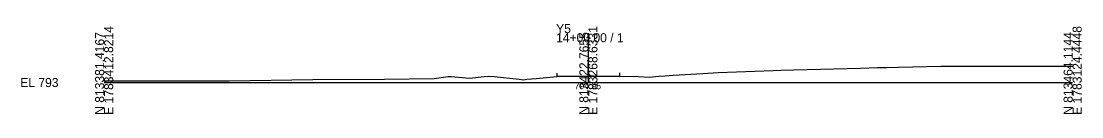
# Model space of a CAD drawing. Extents: x -26 to 1603, y -10 to 6526.
# Drawn here: x 1274.3 to 1602.8, y 990.3 to 1018.1 of the extents above; entities that cross this region are included whole.
import ezdxf

# ---------------------------------------------------------------- set-up
doc = ezdxf.new("R2010")
doc.units = 0
for name, color, linetype in [('Exist Cross Section Cell', 7, 'Continuous'), ('Exist XS Center Line Elevation Label', 7, 'Continuous'), ('Exist XS Ground Line', 7, 'Continuous'), ('Prop XS EOT Tick Mark', 7, 'Continuous'), ('Prop XS Finish Grade Pavement', 7, 'Continuous')]:
    doc.layers.add(name, color=color, linetype=linetype)

msp = doc.modelspace()

# ---------------------------------------------------------------- linework, layer by layer
at = {"layer": 'Exist Cross Section Cell'}
for p, q in [((1450, 1000), (1450, 1015.28)), ((1300, 1000), (1450, 1000)), ((1450, 1000), (1600, 1000))]:
    msp.add_line(p, q, dxfattribs=at)
at = {"layer": 'Exist XS Ground Line'}
for p, q in [((1471.79, 1001.96), (1473.77, 1002.12)), ((1473.77, 1002.12), (1476.26, 1002.26)), ((1476.26, 1002.26), (1485.48, 1002.82)), ((1485.48, 1002.82), (1490.18, 1003.07)), ((1490.18, 1003.07), (1507.29, 1003.73)), ((1507.29, 1003.73), (1509.58, 1003.8)), ((1509.58, 1003.8), (1513.66, 1003.91)), ((1513.66, 1003.91), (1534.25, 1004.49)), ((1534.25, 1004.49), (1539.57, 1004.64)), ((1539.57, 1004.64), (1542.43, 1004.69)), ((1542.43, 1004.69), (1545.94, 1004.76)), ((1545.94, 1004.76), (1559.21, 1005.05)), ((1559.21, 1005.05), (1563.77, 1005.03)), ((1563.77, 1005.03), (1573.89, 1005.05)), ((1573.89, 1005.05), (1575.98, 1005.06)), ((1575.98, 1005.06), (1577.28, 1005.06)), ((1577.28, 1005.06), (1580.84, 1005.05)), ((1580.84, 1005.05), (1593.15, 1005.03)), ((1593.15, 1005.03), (1596.86, 1005.03)), ((1596.86, 1005.03), (1600, 1005.09)), ((1300, 1000.55), (1312.11, 1000.51)), ((1312.11, 1000.51), (1316.09, 1000.51)), ((1316.09, 1000.51), (1334.3, 1000.55)), ((1334.3, 1000.55), (1338.76, 1000.56)), ((1338.76, 1000.56), (1364.65, 1000.91)), ((1364.65, 1000.91), (1386.86, 1001.04)), ((1386.86, 1001.04), (1402.18, 1001.29)), ((1402.18, 1001.29), (1406.6, 1001.9)), ((1406.6, 1001.9), (1407.45, 1001.84)), ((1407.45, 1001.84), (1413.14, 1001.4)), ((1413.14, 1001.4), (1417.73, 1001.92)), ((1417.73, 1001.92), (1419.16, 1001.99)), ((1419.16, 1001.99), (1420.79, 1001.92)), ((1420.79, 1001.92), (1428.58, 1001.09)), ((1428.58, 1001.09), (1429.86, 1000.88)), ((1429.86, 1000.88), (1430.89, 1001.02)), ((1430.89, 1001.02), (1433.78, 1001.27)), ((1433.78, 1001.27), (1434.85, 1001.35)), ((1434.85, 1001.35), (1440.32, 1001.83)), ((1440.32, 1001.83), (1450.07, 1001.95)), ((1450.07, 1001.95), (1451.62, 1001.93)), ((1451.62, 1001.93), (1459.71, 1001.83)), ((1459.71, 1001.83), (1464.91, 1001.95)), ((1464.91, 1001.95), (1465.42, 1001.92)), ((1465.42, 1001.92), (1468.84, 1001.69)), ((1468.84, 1001.69), (1471.79, 1001.96))]:
    msp.add_line(p, q, dxfattribs=at)
at = {"layer": 'Prop XS EOT Tick Mark'}
for p, q in [((1440.31, 1001.95), (1440.31, 1002.95)), ((1459.7, 1001.96), (1459.7, 1002.96))]:
    msp.add_line(p, q, dxfattribs=at)
at = {"layer": 'Prop XS Finish Grade Pavement'}
for p, q in [((1440.32, 1001.95), (1450.07, 1002.08)), ((1450.07, 1002.08), (1451.62, 1002.06)), ((1451.62, 1002.06), (1459.7, 1001.96)), ((1440.31, 1001.95), (1440.32, 1001.95))]:
    msp.add_line(p, q, dxfattribs=at)

# ---------------------------------------------------------------- texts
at = {"layer": 'Exist Cross Section Cell'}
for s, p in [('N 813381.4167', (1300, 990)), ('E 1783412.8214', (1302.8, 990)), ('N 813422.7655', (1450, 990)), ('E 1783268.6331', (1452.8, 990)), ('N 813464.1144', (1600, 990)), ('E 1783124.4448', (1602.8, 990))]:
    msp.add_text(s, height=2.8, rotation=90, dxfattribs=at).set_placement(p)
for s, p in [('Y5', (1440, 1015.28)), ('14+00.00 / 1', (1440, 1012.48)), ('EL 793', (1274, 998.6))]:
    msp.add_text(s, height=2.8, dxfattribs=at).set_placement(p)
at = {"layer": 'Exist XS Center Line Elevation Label'}
msp.add_text('794.95', height=2, dxfattribs=at).set_placement((1445.74, 997.95))

doc.saveas('drawing.dxf')
